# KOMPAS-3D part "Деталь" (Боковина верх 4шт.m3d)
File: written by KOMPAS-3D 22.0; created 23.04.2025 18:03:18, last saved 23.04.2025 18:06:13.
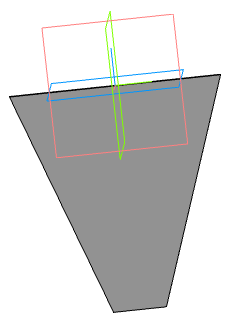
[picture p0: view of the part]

Document properties: Автор: Admin; Полное имя файла: D:\28.11.2016\3D модели\Абилимпикс\2025\Воронка квадратная\Боковина верх 4шт.m3d

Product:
- Part/product: Деталь
    Масса: 0.050341

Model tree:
1. Эскиз:1
2. Элемент выдавливания:1
     Расстояние 1 = 1.5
